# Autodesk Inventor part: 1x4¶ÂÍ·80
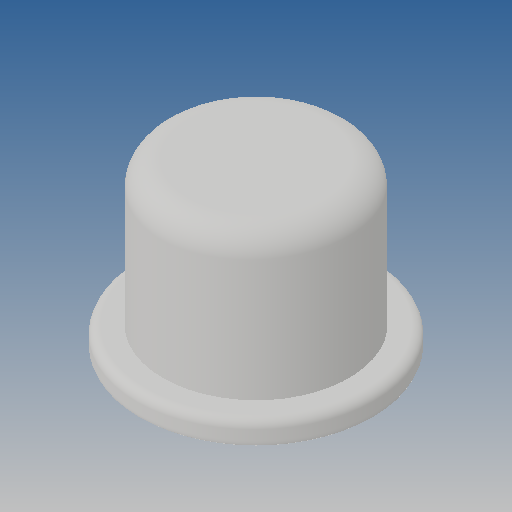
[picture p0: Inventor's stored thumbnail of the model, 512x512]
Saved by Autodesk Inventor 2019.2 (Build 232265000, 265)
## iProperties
Created: 2013-07
Part Number: 1x4¶ÂÍ·80
Material: Ogólny
Document SubType Name: Modeling
Designer: CADENGINEERING4
Density: 1 g/cm^3
Appearance: Domyślna
Author: CADENGINEERING4
Revision Number: ÈÎºÎ
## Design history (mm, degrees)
feature "Ô²½Ç1"
node "Bryła1"
